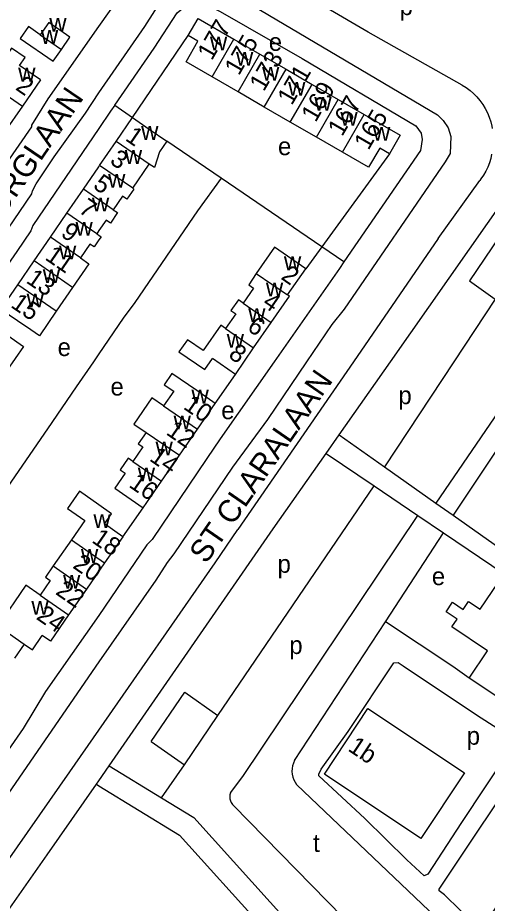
# Model space of a CAD drawing. Extents: x 159045 to 160918, y 380454 to 382516.
# Drawn here: x 160681.9 to 160786.8, y 381628.9 to 381826.9 of the extents above; entities that cross this region are included whole.
import ezdxf

# ---------------------------------------------------------------- set-up
doc = ezdxf.new("R2010")
doc.units = 0
for name, color, linetype in [('BLT_Basislijn', 7, 'Continuous'), ('BLT_Bebouwing', 7, 'Continuous'), ('BLT_Centroide', 7, 'Continuous'), ('BLT_Huisnummer', 7, 'Continuous'), ('BLT_Huisnummer_ tussenligend', 7, 'Continuous'), ('BLT_Huisnummer_zonder_bebouwing', 7, 'Continuous'), ('BLT_Onderverdeling_panden', 7, 'Continuous'), ('BLT_Plantopo', 7, 'Continuous'), ('BLT_Straatnaam', 7, 'Continuous')]:
    doc.layers.add(name, color=color, linetype=linetype)

msp = doc.modelspace()

# ---------------------------------------------------------------- linework, layer by layer
at = {"layer": 'BLT_Basislijn'}
for p, q in [((160707.53, 381804.6), (160719.96, 381822.93)), ((160703.54, 381807.37), (160707.53, 381804.6)), ((160727.37, 381791.04), (160715.21, 381799.33)), ((160764.97, 381796.52), (160749.82, 381775.73)), ((160749.82, 381775.73), (160727.37, 381791.04)), ((160775.88, 381777.54), (160785.14, 381790.55)), ((160765.18, 381750), (160791.62, 381787.74)), ((160775.88, 381777.54), (160756.93, 381750)), ((160749.82, 381775.73), (160746.24, 381770.81)), ((160754.77, 381772.35), (160749.82, 381775.73)), ((160700, 381751.8), (160698.77, 381750)), ((160756.93, 381750), (160731.09, 381712.46)), ((160753.75, 381733.69), (160765.18, 381750)), ((160779.37, 381750), (160763.84, 381726.54)), ((160796.89, 381750), (160775.34, 381718.39)), ((160726.02, 381740.7), (160730.53, 381747.18)), ((160794.34, 381738.47), (160779.18, 381715.67)), ((160750.81, 381729.49), (160753.75, 381733.69)), ((160753.75, 381733.69), (160763.84, 381726.54)), ((160738.99, 381712.61), (160750.81, 381729.49)), ((160750.81, 381729.49), (160761.56, 381722.22)), ((160763.84, 381726.54), (160775.34, 381718.39)), ((160726.61, 381670.92), (160761.56, 381722.22)), ((160761.56, 381722.22), (160771.33, 381715.61)), ((160775.34, 381718.39), (160779.18, 381715.67)), ((160705.38, 381710.87), (160709.89, 381717.34)), ((160771.33, 381715.61), (160777.07, 381711.72)), ((160779.18, 381715.67), (160792.83, 381705.99)), ((160702.31, 381659.63), (160738.99, 381712.61)), ((160764.04, 381691.82), (160777.07, 381711.72)), ((160777.07, 381711.72), (160790.56, 381702.59)), ((160743.74, 381660.82), (160764.04, 381691.82)), ((160683.31, 381686.87), (160681.15, 381683.71)), ((160700, 381682.87), (160668.28, 381636.87)), ((160711.72, 381665.12), (160719.23, 381676.13)), ((160719.23, 381676.13), (160726.61, 381670.92)), ((160719.11, 381659.9), (160726.61, 381670.92)), ((160693.52, 381658.28), (160700, 381667.6)), ((160711.72, 381665.12), (160719.11, 381659.9)), ((160673.29, 381629.36), (160693.52, 381658.28)), ((160700, 381656.29), (160702.31, 381659.63)), ((160702.31, 381659.63), (160714.04, 381652.46)), ((160714.04, 381652.46), (160719.11, 381659.9)), ((160699.46, 381655.51), (160700, 381656.29)), ((160699.46, 381655.51), (160700, 381655.18)), ((160744.28, 381655.37), (160788.35, 381613.43))]:
    msp.add_line(p, q, dxfattribs=at)
for points in [[(160781.21, 381811.89), (160760.2, 381823.71), (160711.81, 381852)], [(160700, 381824.95), (160704.79, 381831.78), (160708.59, 381838.97)], [(160700, 381810.17), (160710.29, 381824.96), (160714.24, 381831.21), (160716.25, 381833.77), (160718.22, 381835.05), (160719.92, 381835.74), (160722.98, 381835.83), (160723.84, 381835.63), (160725.92, 381834.72), (160775.67, 381805.22), (160776.94, 381803.95), (160778.06, 381802.35), (160778.71, 381800.38), (160778.49, 381796.6), (160777.38, 381794.71), (160754.8, 381761.74), (160752.04, 381758.34), (160746.41, 381750)], [(160703.54, 381807.37), (160712.34, 381820.14), (160717.53, 381828.03), (160719.12, 381829.36), (160720.97, 381830), (160724, 381829.93), (160727.08, 381828.34), (160745.45, 381817.83), (160770.88, 381802.74), (160772.06, 381801.14), (160772.3, 381799.67), (160771.9, 381797.22), (160754.77, 381772.35)], [(160649.16, 381750), (160657.32, 381762.17), (160659.67, 381765.11), (160666.49, 381775.76), (160685, 381802.51), (160685.01, 381802.91), (160688.68, 381808.78), (160700, 381824.95)], [(160781.21, 381811.89), (160782.11, 381811.31), (160782.96, 381810.67), (160783.76, 381809.97), (160784.5, 381809.21), (160785.18, 381808.39), (160785.81, 381807.53), (160786.36, 381806.62), (160786.85, 381805.68), (160787.26, 381804.7), (160787.6, 381803.69), (160787.86, 381802.65), (160787.94, 381802.2)], [(160659.26, 381750), (160665.72, 381759.07), (160666.29, 381760.14), (160685.05, 381787.58), (160685.16, 381788.23), (160686.01, 381789.79), (160690.01, 381795.82), (160697, 381805.62), (160700, 381810.17)], [(160703.54, 381807.37), (160702.64, 381806.06), (160700, 381802.18)], [(160700, 381802.18), (160685.22, 381780.46), (160684.77, 381779.3), (160681.67, 381774.68), (160664.54, 381750)], [(160787.79, 381796.42), (160787.58, 381795.43), (160787.29, 381794.46), (160786.93, 381793.51), (160786.49, 381792.6), (160785.98, 381791.72), (160785.4, 381790.89), (160785.14, 381790.55)], [(160727.37, 381791.04), (160722.08, 381783.75), (160708.05, 381763.26), (160705.45, 381759.76), (160700, 381751.8)], [(160796.13, 381787.74), (160782.84, 381768.12), (160788.62, 381763.98), (160779.37, 381750)], [(160754.77, 381772.35), (160753.76, 381770.88), (160739.15, 381750)], [(160698.77, 381750), (160694.92, 381744.38), (160688.5, 381735.04)], [(160746.41, 381750), (160737.72, 381737.11), (160729.87, 381726.45), (160716.76, 381707.03), (160715.3, 381705.15), (160712.74, 381701.13), (160700, 381682.87)], [(160739.15, 381750), (160727.1, 381732.78), (160724.15, 381728.4)], [(160688.5, 381735.04), (160635.26, 381657.6)], [(160724.15, 381728.4), (160711.95, 381710.25), (160710.74, 381709.07), (160700, 381693.27)], [(160729.43, 381653.63), (160732.2, 381657.27), (160771.33, 381715.61)], [(160700, 381667.6), (160726.03, 381705.02), (160731.09, 381712.46)], [(160700, 381693.27), (160688.1, 381676.23), (160683.09, 381668), (160661.39, 381636.73)], [(160782.77, 381679.24), (160779.13, 381681.85), (160764.04, 381691.82)], [(160781.06, 381646.98), (160773.5, 381635.43), (160772.7, 381635.07), (160768.85, 381638.6), (160759.45, 381647.87), (160749.17, 381657.38), (160749.17, 381657.79), (160749.68, 381658.91), (160755.76, 381667.34), (160765.91, 381682.7), (160766.9, 381682.73), (160768.01, 381682.03), (160784.61, 381670.88), (160792.44, 381665.88), (160792.76, 381665.5), (160791.61, 381662.96), (160781.06, 381646.98)], [(160798.56, 381642.75), (160785.69, 381623.43), (160785.17, 381623.43), (160784.3, 381623.95), (160777.23, 381630.8), (160776.05, 381631.69), (160776.05, 381632.08), (160796.4, 381662.58), (160797.73, 381662.13), (160806.82, 381656.14), (160806.73, 381655.4), (160798.56, 381642.75)], [(160743.74, 381660.82), (160743.48, 381660.24), (160743.3, 381659.64), (160743.2, 381659.01), (160743.17, 381658.38), (160743.23, 381657.75), (160743.36, 381657.14), (160743.57, 381656.54), (160743.86, 381655.98), (160744.21, 381655.46), (160744.28, 381655.37)], [(160675.89, 381621.88), (160688.46, 381639.71), (160699.46, 381655.51)], [(160700, 381655.18), (160709.01, 381649.68)], [(160714.04, 381652.46), (160721.24, 381648.06), (160760.12, 381604.96)], [(160729.43, 381653.63), (160729.3, 381653.19), (160729.25, 381652.73), (160729.29, 381652.28), (160729.4, 381651.83), (160729.58, 381651.41), (160729.84, 381651.03), (160730.06, 381650.78)], [(160730.06, 381650.78), (160754.56, 381625.8), (160757.08, 381624.69)], [(160709.01, 381649.68), (160718.01, 381644.17), (160755.44, 381602.68)]]:
    msp.add_lwpolyline(points, dxfattribs=at)
at = {"layer": 'BLT_Bebouwing'}
for p, q in [((160691.62, 381819.81), (160693.54, 381822.6)), ((160730.18, 381822.13), (160736.01, 381818.77)), ((160689.82, 381817.21), (160691.62, 381819.81)), ((160736.01, 381818.77), (160741.84, 381815.4)), ((160741.84, 381815.4), (160747.67, 381812.03)), ((160686.94, 381813.02), (160682.91, 381807.17)), ((160731.14, 381810.34), (160725.31, 381813.71)), ((160747.67, 381812.03), (160753.5, 381808.66)), ((160736.97, 381806.97), (160731.14, 381810.34)), ((160682.91, 381807.17), (160678.98, 381801.46)), ((160742.8, 381803.6), (160736.97, 381806.97)), ((160753.5, 381808.66), (160759.33, 381805.29)), ((160703.87, 381799.26), (160707.53, 381804.6)), ((160748.63, 381800.24), (160742.8, 381803.6)), ((160700.16, 381793.86), (160703.87, 381799.26)), ((160754.46, 381796.87), (160748.63, 381800.24)), ((160696.54, 381788.59), (160700, 381793.62)), ((160700, 381793.62), (160700.16, 381793.86)), ((160707.59, 381788.8), (160711.28, 381794.19)), ((160692.86, 381783.21), (160696.54, 381788.59)), ((160689.18, 381777.85), (160692.86, 381783.21)), ((160700, 381779.32), (160699.53, 381778.64)), ((160685.55, 381772.56), (160689.18, 381777.85)), ((160699.53, 381778.64), (160700, 381778.32)), ((160681.9, 381767.23), (160685.55, 381772.56)), ((160742.17, 381764.94), (160746.24, 381770.81)), ((160678.11, 381761.71), (160681.9, 381767.23)), ((160694.13, 381766.63), (160690.48, 381761.31)), ((160734.6, 381753.1), (160738.51, 381758.79)), ((160730.53, 381747.18), (160734.6, 381753.1)), ((160730.53, 381747.18), (160725.37, 381750.73)), ((160722.06, 381734.91), (160726.02, 381740.7)), ((160710.55, 381734.19), (160708.82, 381731.68)), ((160718.06, 381729.1), (160722.06, 381734.91)), ((160713.98, 381723.28), (160718.06, 381729.1)), ((160709.89, 381717.34), (160713.98, 381723.28)), ((160696.86, 381714.47), (160693.89, 381710.2)), ((160693.89, 381710.2), (160689.8, 381704.35)), ((160705.38, 381710.87), (160701.28, 381705.01)), ((160701.28, 381705.01), (160697.22, 381699.17)), ((160697.22, 381699.17), (160693.25, 381693.38)), ((160685.16, 381685.59), (160687.34, 381688.79)), ((160683.31, 381686.87), (160685.16, 381685.59)), ((160793.08, 381672.36), (160782.77, 381679.24))]:
    msp.add_line(p, q, dxfattribs=at)
for points in [[(160719.96, 381822.93), (160722.17, 381826.76), (160730.18, 381822.13)], [(160686.92, 381823.14), (160684.3, 381825), (160682.43, 381822.3), (160689.82, 381817.21)], [(160693.54, 381822.6), (160688.84, 381825.85), (160686.92, 381823.14)], [(160725.31, 381813.71), (160719.48, 381817.08), (160722.14, 381821.67), (160719.96, 381822.93)], [(160686.94, 381813.02), (160682.28, 381816.23), (160683.5, 381818.01), (160680.45, 381820.12), (160677.62, 381816.02), (160677.23, 381816.29), (160674.79, 381812.76)], [(160759.33, 381805.29), (160767.35, 381800.65), (160764.97, 381796.52)], [(160707.53, 381804.6), (160711.25, 381802.05), (160715.21, 381799.33)], [(160715.21, 381799.33), (160713.59, 381796.97), (160712.41, 381793.42), (160711.28, 381794.19)], [(160764.97, 381796.52), (160762.77, 381797.79), (160760.29, 381793.5), (160754.46, 381796.87)], [(160707.59, 381788.8), (160707.83, 381788.6), (160706.27, 381786.33), (160705.29, 381787), (160703.23, 381784)], [(160703.23, 381784), (160704.18, 381783.35), (160702.58, 381781.02), (160701.62, 381781.68), (160700, 381779.32)], [(160700, 381777.24), (160698.93, 381775.68), (160697.99, 381776.32), (160695.89, 381773.26)], [(160700, 381778.32), (160700.5, 381777.97), (160700, 381777.24)], [(160746.24, 381770.81), (160739.26, 381775.61), (160735.2, 381769.72)], [(160695.89, 381773.26), (160697.76, 381771.91), (160694.13, 381766.63)], [(160735.2, 381769.72), (160733.49, 381767.24), (160734.58, 381766.49), (160732.26, 381763.12)], [(160732.26, 381763.12), (160731.19, 381763.85), (160729.53, 381761.43), (160730.59, 381760.7), (160728.34, 381757.42)], [(160738.51, 381758.79), (160742.59, 381764.65), (160742.17, 381764.94)], [(160690.48, 381761.31), (160686.71, 381755.81), (160684.78, 381757.13), (160681.84, 381759.15), (160678.11, 381761.71)], [(160675.78, 381758.48), (160679.63, 381755.84), (160683.15, 381753.43), (160679.46, 381748.04)], [(160728.34, 381757.42), (160727.24, 381758.18), (160723.33, 381752.5), (160719.78, 381754.94), (160717.9, 381752.2), (160723.66, 381748.25)], [(160723.66, 381748.25), (160725.37, 381750.73)], [(160726.02, 381740.7), (160721.88, 381743.56), (160716.34, 381747.38), (160714.61, 381744.86), (160716.73, 381743.4), (160714.45, 381740.11)], [(160714.45, 381740.11), (160711.86, 381741.9), (160707.85, 381736.08), (160710.55, 381734.19)], [(160708.82, 381731.68), (160709.86, 381730.97), (160707.6, 381727.68)], [(160707.6, 381727.68), (160706.53, 381728.42), (160704.77, 381725.87), (160705.89, 381725.1), (160703.55, 381721.71), (160709.89, 381717.34)], [(160700.02, 381717.98), (160695.67, 381721.03), (160692.98, 381717.2), (160696.86, 381714.47)], [(160705.38, 381710.87), (160701.23, 381713.74), (160702.81, 381716.01), (160700.02, 381717.98)], [(160689.8, 381704.35), (160688.05, 381701.83), (160689.15, 381701.08), (160686.9, 381697.84)], [(160782.77, 381679.24), (160786.86, 381685.37), (160778.89, 381690.69), (160780.07, 381692.46), (160777.63, 381694.09), (160779.06, 381696.24), (160781.46, 381694.63), (160782.65, 381696.41), (160785.26, 381694.66), (160790.56, 381702.59)], [(160686.9, 381697.84), (160683.7, 381700.06), (160677.4, 381690.96), (160683.31, 381686.87)], [(160693.25, 381693.38), (160689.19, 381687.51), (160687.34, 381688.79)]]:
    msp.add_lwpolyline(points, dxfattribs=at)
at = {"layer": 'BLT_Onderverdeling_panden'}
for p, q in [((160686.92, 381823.14), (160691.62, 381819.81)), ((160725.31, 381813.71), (160730.18, 381822.13)), ((160731.14, 381810.34), (160736.01, 381818.77)), ((160736.97, 381806.97), (160741.84, 381815.4)), ((160674.79, 381812.76), (160682.91, 381807.17)), ((160742.8, 381803.6), (160747.67, 381812.03)), ((160748.63, 381800.24), (160753.5, 381808.66)), ((160754.46, 381796.87), (160759.33, 381805.29)), ((160711.28, 381794.19), (160703.87, 381799.26)), ((160707.59, 381788.8), (160700.16, 381793.86)), ((160700, 381786.22), (160696.54, 381788.59)), ((160703.23, 381784), (160700, 381786.22)), ((160699.53, 381778.64), (160692.86, 381783.21)), ((160695.89, 381773.26), (160689.18, 381777.85)), ((160694.13, 381766.63), (160685.55, 381772.56)), ((160735.2, 381769.72), (160742.17, 381764.94)), ((160690.48, 381761.31), (160681.9, 381767.23)), ((160732.26, 381763.12), (160738.51, 381758.79)), ((160728.34, 381757.42), (160734.6, 381753.1)), ((160714.45, 381740.11), (160722.06, 381734.91)), ((160710.55, 381734.19), (160718.06, 381729.1)), ((160707.6, 381727.68), (160713.98, 381723.28)), ((160693.89, 381710.2), (160701.28, 381705.01)), ((160689.8, 381704.35), (160697.22, 381699.17)), ((160686.9, 381697.84), (160693.25, 381693.38))]:
    msp.add_line(p, q, dxfattribs=at)
at = {"layer": 'BLT_Plantopo'}
msp.add_lwpolyline([(160750.4, 381657.81), (160760.15, 381672.45), (160781.74, 381658.07), (160771.99, 381643.43)], close=True, dxfattribs=at)

# ---------------------------------------------------------------- texts
at = {"layer": 'BLT_Centroide'}
for s, p in [('p', (160767.24, 381827.52)), ('w', (160688.92, 381823.81)), ('w', (160687.05, 381821.09)), ('w', (160724.83, 381819.61)), ('e', (160737.99, 381819.53)), ('w', (160730.66, 381816.23)), ('w', (160681.97, 381812.66)), ('w', (160736.48, 381812.88)), ('w', (160742.31, 381809.5)), ('w', (160748.16, 381806.12)), ('w', (160753.98, 381802.77)), ('w', (160709.45, 381799.62)), ('w', (160761.27, 381799.41)), ('e', (160740.04, 381796.2)), ('w', (160705.8, 381794.25)), ('w', (160702.07, 381788.94)), ('w', (160698.46, 381783.62)), ('w', (160694.78, 381778.22)), ('w', (160691.09, 381772.91)), ('w', (160741.37, 381770.47)), ('w', (160687.47, 381767.59)), ('w', (160737.34, 381764.62)), ('w', (160683.85, 381762.19)), ('w', (160733.38, 381758.91)), ('w', (160728.58, 381753.16)), ('e', (160690.78, 381751.28)), ('e', (160702.6, 381742.45)), ('w', (160720.7, 381740.66)), ('p', (160766.96, 381740.52)), ('e', (160727.36, 381737.16)), ('w', (160716.71, 381734.88)), ('w', (160712.67, 381729.09)), ('w', (160708.7, 381723.28)), ('w', (160698.78, 381712.84)), ('w', (160696, 381705.03)), ('p', (160739.94, 381702.81)), ('w', (160692, 381699.28)), ('e', (160774.43, 381700.05)), ('w', (160684.92, 381693.44)), ('p', (160742.58, 381684.65)), ('p', (160782.23, 381664.36)), ('t', (160747.88, 381640.39))]:
    msp.add_text(s, height=4, dxfattribs=at).set_placement(p)
at = {"layer": 'BLT_Huisnummer'}
for s, rotation, p in [('177', 59.9834, (160725.24, 381817.2)), ('173', 59.9797, (160736.87, 381810.27)), ('2', 325.4117, (160681.17, 381810.99)), ('169', 59.9811, (160748.45, 381803.37)), ('165', 59.9911, (160760.26, 381797.13)), ('1', 325.5738, (160705.69, 381799.66)), ('5', 325.5615, (160698.49, 381788.97)), ('9', 325.5668, (160691.26, 381778.23)), ('2', 325.3196, (160740.5, 381768.64)), ('15', 325.5592, (160680.1, 381762.35)), ('8', 325.3304, (160728.74, 381751.11)), ('10', 325.3688, (160718.67, 381739.62)), ('16', 325.364, (160706.5, 381722.15)), ('18', 325.37, (160698.22, 381709.75)), ('24', 325.3677, (160685.8, 381692.59))]:
    msp.add_text(s, height=4, rotation=rotation, dxfattribs=at).set_placement(p)
at = {"layer": 'BLT_Huisnummer_ tussenligend'}
for s, rotation, p in [('175', 59.9797, (160731.3, 381813.83)), ('171', 59.9811, (160743.12, 381807.16)), ('167', 59.9911, (160754.38, 381800.21)), ('3', 325.5738, (160702.23, 381794.5)), ('7', 325.5615, (160695.24, 381783.57)), ('11', 325.5668, (160687.76, 381772.99)), ('13', 325.5668, (160683.53, 381767.83)), ('4', 325.3196, (160736.32, 381762.62)), ('6', 325.3196, (160732.92, 381757.21)), ('12', 325.3688, (160714.82, 381733.89)), ('14', 325.3688, (160711.1, 381728.03)), ('20', 325.37, (160693.96, 381704.05)), ('22', 325.37, (160690.11, 381698.16))]:
    msp.add_text(s, height=4, rotation=rotation, dxfattribs=at).set_placement(p)
at = {"layer": 'BLT_Huisnummer_zonder_bebouwing'}
msp.add_text('1b', height=4, rotation=326.2701, dxfattribs=at).set_placement((160755.46, 381663.17))
at = {"layer": 'BLT_Straatnaam'}
for s, rotation, p in [('RAPELENBURGLAAN', 55.7281, (160658.51, 381752.9)), ('ST CLARALAAN', 55.3554, (160723.98, 381704.61))]:
    msp.add_text(s, height=5, rotation=rotation, dxfattribs=at).set_placement(p)

doc.saveas('drawing.dxf')
